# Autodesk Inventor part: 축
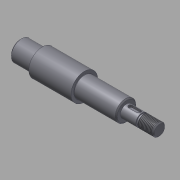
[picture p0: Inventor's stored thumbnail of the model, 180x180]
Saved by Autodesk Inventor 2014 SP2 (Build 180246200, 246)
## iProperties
Created: 2015-12
Part Number: 축
Material: 강철, 연강
Document SubType Name: Modeling
Designer: mdu
Density: 7.86 g/cm^3
Appearance: 강철
CustomPartVersion: 1
Author: mdu
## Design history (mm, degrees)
sketch "스케치5"
  geometry: L1 (0, 0)-(135, 0); L2 (0, 0)-(135, 0); L3 (135, 0)-(135, 6); L4 (103, 6)-(103, 10); L5 (103, 10)-(62, 10); L6 (62, 10)-(62, 13); L7 (62, 13)-(21, 13); L8 (21, 13)-(21, 10); L9 (21, 10)-(0, 10); L10 (0, 10)-(0, 0); L11 (118, 6)-(118, 5); L12 (118, 5)-(120, 5); L13 (120, 5)-(120, 6); L14 (135, 6)-(120, 6); L15 (118, 6)-(103, 6)
  constraints: 31 end point, 12 perpendicular, 9 parallel, 1 collinear, 1 horizontal
  dimensions: "d43" = 20 diameter of L9 L1; "d44" = 26 diameter of L7 L1; "d45" = 20 diameter of L5 L2; "d47" = 41 distance of L6.end L7.end; "d48" = 32 distance between parallel lines of L3 L4; "d50" = 21 distance of L8.end L9.end; "d52" = 12 diameter of L14 L1; "d53" = 15 distance between parallel lines of L3 L13; "d54" = 2 distance of L11.end L12.end; "d55" = 1 distance between parallel lines of L14 L12; "d64" = 135 distance of L1.start L1.end
revolve "회전4" sketch "스케치5" stored, may be unused: angle "d51" = 90 deg
feature "스레드6" dims "d56" = 10, "d57" = 0
chamfer "모따기6" distance "d32" = 1; stored, may be unused: second distance "d33" = 0.4, angle "d34" = 45 deg
chamfer "모따기5" distance "d27" = 1; stored, may be unused: second distance "d28" = 0.125, angle "d29" = 45 deg
fillet "모깎기1" dims "d17" = 0.3
fillet "모깎기2" dims "d18" = 0.3
chamfer "모따기3" distance "d19" = 1; stored, may be unused: second distance "d20" = 1, angle "d21" = 45 deg
node "작업 평면1"
sketch "스케치6"
  geometry: L1 (-3.5, 2)-(4.5, 2); L2 (4.5, -2)-(-3.5, -2); L3 (-7.5, 9)-(-7.5, -9) reference; A1 r 2 centre (4.5, 0) between (4.5, -2) and (4.5, 2); A2 r 2 centre (-3.5, 0) between (-3.5, 2) and (-3.5, -2); 1 further point
  constraints: 4 end point, 4 point on circle, 4 tangent, 2 centre point, 1 horizontal, 1 horizontal alignment, 1 parallel
  dimensions: "d59" = 2 distance edge to line of A2 L3; "d60" = 12 dimension on A1 A2; "d61" = 4 distance between parallel lines of L2 L1
extrude "돌출1" cut sketch "스케치6" distance "d62" = 2.3; taper "d63" = 0 deg
node "솔리드1"
node "솔리드2"
other parameters: "d46" = 12
